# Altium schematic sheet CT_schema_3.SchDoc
size 178 x 159 mm
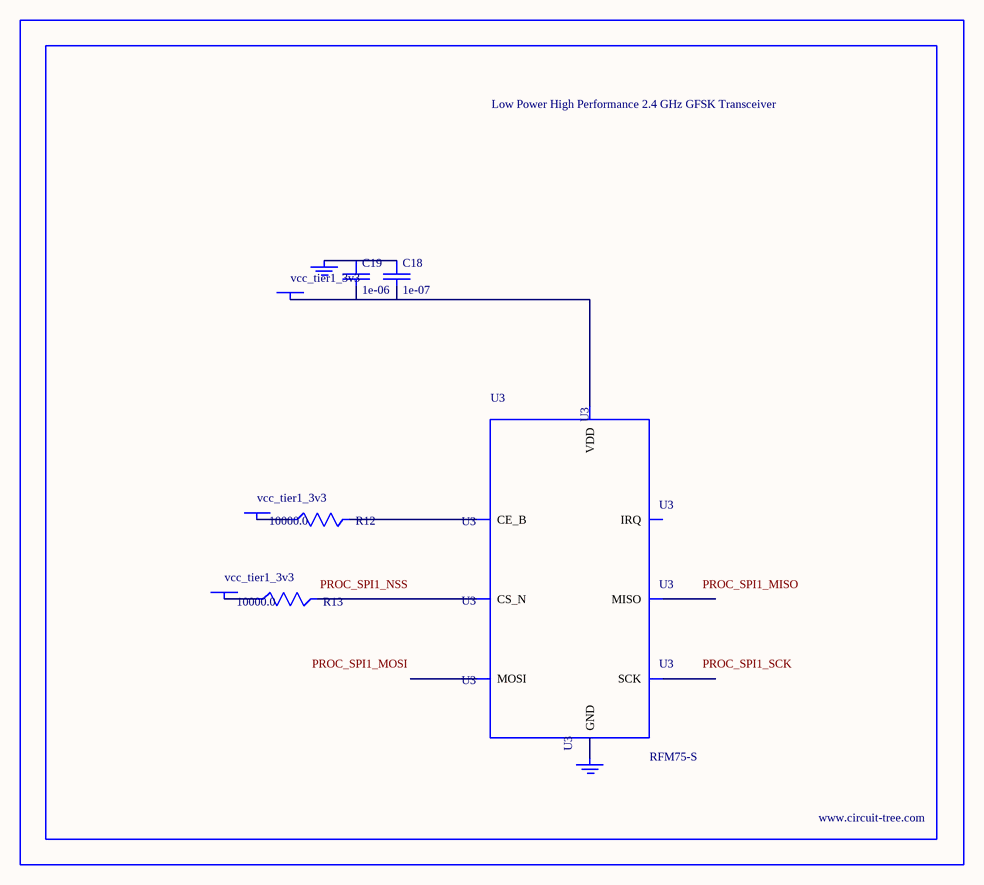
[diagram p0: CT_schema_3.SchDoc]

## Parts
BORDER2  (no value)
C18  1e-07  [C0402]
C19  1e-06  [C0603]
GND_INSTANCE_2_0  (no value)
GND_INSTANCE_2_1  (no value)
POWER_INSTANCE_2_0  vcc_tier1_3v3
POWER_INSTANCE_2_1  vcc_tier1_3v3
POWER_INSTANCE_2_2  vcc_tier1_3v3
R12  10000.0  [R0603]
R13  10000.0  [R0603]
U3  RFM75-S  [RFM75-S]

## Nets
NetC18_1: C18.1 C19.1 GND_INSTANCE_2_0.0(GND)
NetC18_2: C18.2 C19.2 POWER_INSTANCE_2_0.0(PWR) U3.2(VDD)
NetGND_INSTANCE_2_1_0: GND_INSTANCE_2_1.0(GND) U3.1(GND)
NetPOWER_INSTANCE_2_1_0: POWER_INSTANCE_2_1.0(PWR) R12.1
NetPOWER_INSTANCE_2_2_0: POWER_INSTANCE_2_2.0(PWR) R13.1
NetR12_2: R12.2 U3.3(CE_B)
NetR13_2: R13.2 U3.4(CS_N)

Not connected (* = marked no-connect by the designer): U3 5(SCK) 6(MOSI) 7(MISO) 8(IRQ)

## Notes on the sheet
- Labels drawn without touching a wire or pin: PROC_SPI1_MISO, PROC_SPI1_MOSI, PROC_SPI1_NSS, PROC_SPI1_SCK

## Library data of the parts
BORDER2 = BORDER_PAGE2
C18 = C0402C104K3RACTU
C19 = C0603C105K3RACTU
GND_INSTANCE_2_0 GND_INSTANCE_2_1 = GND
POWER_INSTANCE_2_0-POWER_INSTANCE_2_2 = PWR
R12 R13 = RC0603JR-0710KL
